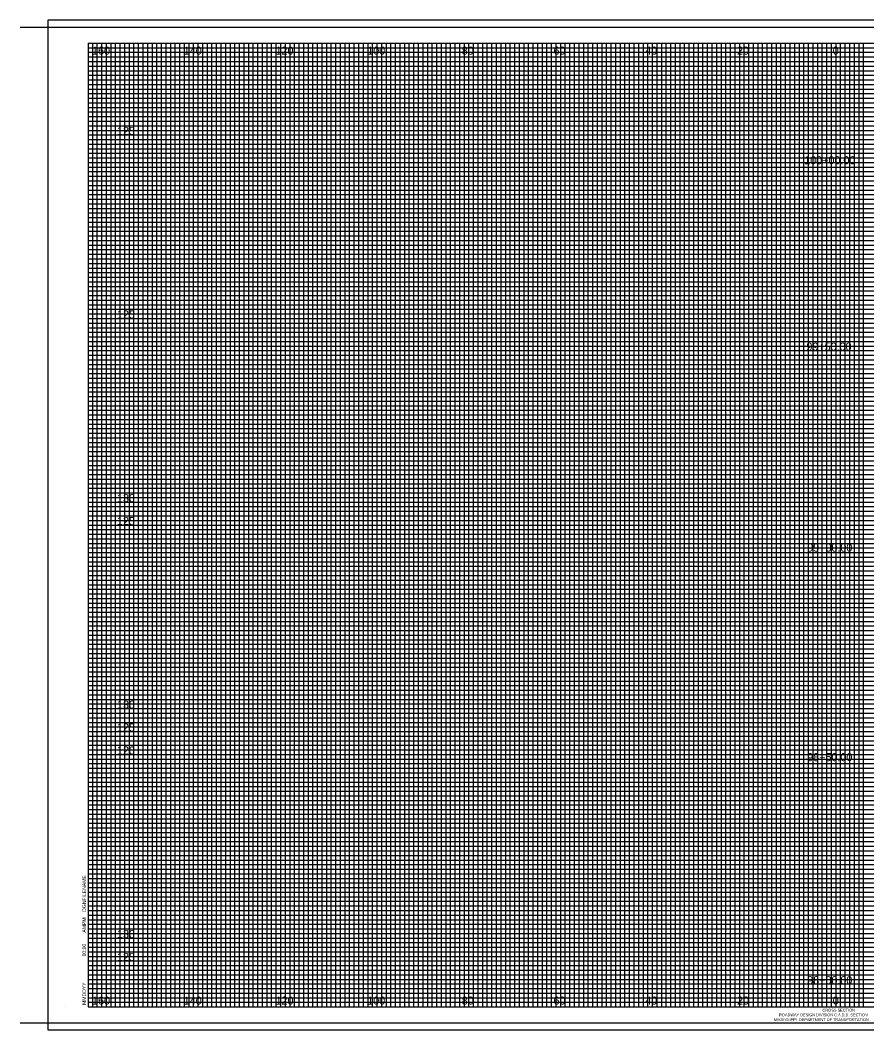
# Model space of a CAD drawing. Extents: x -3604 to 2303, y -13 to 9543.
# Drawn here: x -3604.5 to -3420, y 6454.1 to 6674.1 of the extents above; entities that cross this region are included whole.
import ezdxf

# ---------------------------------------------------------------- set-up
doc = ezdxf.new("R2010")
doc.units = 0
for name, color, linetype in [('SHEET_BORDER', 7, 'Continuous'), ('SHEET_BORDER_TX', 7, 'Continuous'), ('SHEET_DATE_DGN_TX', 7, 'Continuous'), ('SHEET_PLOTTING_SHAPE', 7, 'Continuous'), ('XS_SHEET_LABELS_ELEVATION', 7, 'Continuous'), ('XS_SHEET_LABELS_OFFSET', 7, 'Continuous'), ('XS_SHEET_LABELS_STATION', 7, 'Continuous'), ('XS_SHEET_MAJOR_GRIDS', 7, 'Continuous'), ('XS_SHEET_MEDIUM_GRIDS', 7, 'Continuous'), ('XS_SHEET_MINOR_GRIDS', 7, 'Continuous')]:
    doc.layers.add(name, color=color, linetype=linetype)

msp = doc.modelspace()

# ---------------------------------------------------------------- linework, layer by layer
at = {"layer": 'SHEET_BORDER'}
for p, q in [((-3604.48, 6672.59), (-3252.48, 6672.59)), ((-3589.68, 6669.09), (-3254.68, 6669.09)), ((-3589.68, 6669.09), (-3589.68, 6459.09)), ((-3445.68, 6459.09), (-3445.68, 6669.09)), ((-3594.68, 6459.09), (-3594.68, 6459.09)), ((-3589.68, 6459.09), (-3254.68, 6459.09)), ((-3604.48, 6455.59), (-3252.48, 6455.59))]:
    msp.add_line(p, q, dxfattribs=at)
at = {"layer": 'SHEET_PLOTTING_SHAPE'}
msp.add_lwpolyline([(-3598.48, 6454.09), (-3252.48, 6454.09), (-3252.48, 6674.09), (-3598.48, 6674.09)], close=True, dxfattribs=at)
at = {"layer": 'XS_SHEET_MAJOR_GRIDS'}
for p, q in [((-3584.68, 6459.09), (-3584.68, 6669.09)), ((-3574.68, 6459.09), (-3574.68, 6669.09)), ((-3564.68, 6459.09), (-3564.68, 6669.09)), ((-3554.68, 6459.09), (-3554.68, 6669.09)), ((-3544.68, 6459.09), (-3544.68, 6669.09)), ((-3534.68, 6459.09), (-3534.68, 6669.09)), ((-3524.68, 6459.09), (-3524.68, 6669.09)), ((-3514.68, 6459.09), (-3514.68, 6669.09)), ((-3504.68, 6459.09), (-3504.68, 6669.09)), ((-3494.68, 6459.09), (-3494.68, 6669.09)), ((-3484.68, 6459.09), (-3484.68, 6669.09)), ((-3474.68, 6459.09), (-3474.68, 6669.09)), ((-3464.68, 6459.09), (-3464.68, 6669.09)), ((-3454.68, 6459.09), (-3454.68, 6669.09)), ((-3444.68, 6459.09), (-3444.68, 6669.09)), ((-3434.68, 6459.09), (-3434.68, 6669.09)), ((-3424.68, 6459.09), (-3424.68, 6669.09)), ((-3589.68, 6659.09), (-3254.68, 6659.09)), ((-3589.68, 6649.09), (-3254.68, 6649.09)), ((-3589.68, 6639.09), (-3254.68, 6639.09)), ((-3589.68, 6629.09), (-3254.68, 6629.09)), ((-3589.68, 6619.09), (-3254.68, 6619.09)), ((-3589.68, 6609.09), (-3254.68, 6609.09)), ((-3589.68, 6599.09), (-3254.68, 6599.09)), ((-3589.68, 6589.09), (-3254.68, 6589.09)), ((-3589.68, 6579.09), (-3254.68, 6579.09)), ((-3589.68, 6569.09), (-3254.68, 6569.09)), ((-3589.68, 6559.09), (-3254.68, 6559.09)), ((-3589.68, 6549.09), (-3254.68, 6549.09)), ((-3589.68, 6539.09), (-3254.68, 6539.09)), ((-3589.68, 6529.09), (-3254.68, 6529.09)), ((-3589.68, 6519.09), (-3254.68, 6519.09)), ((-3589.68, 6509.09), (-3254.68, 6509.09)), ((-3589.68, 6499.09), (-3254.68, 6499.09)), ((-3589.68, 6489.09), (-3254.68, 6489.09)), ((-3589.68, 6479.09), (-3254.68, 6479.09)), ((-3589.68, 6469.09), (-3254.68, 6469.09))]:
    msp.add_line(p, q, dxfattribs=at)
at = {"layer": 'XS_SHEET_MEDIUM_GRIDS'}
for p, q in [((-3579.68, 6459.09), (-3579.68, 6669.09)), ((-3569.68, 6459.09), (-3569.68, 6669.09)), ((-3559.68, 6459.09), (-3559.68, 6669.09)), ((-3549.68, 6459.09), (-3549.68, 6669.09)), ((-3539.68, 6459.09), (-3539.68, 6669.09)), ((-3529.68, 6459.09), (-3529.68, 6669.09)), ((-3519.68, 6459.09), (-3519.68, 6669.09)), ((-3509.68, 6459.09), (-3509.68, 6669.09)), ((-3499.68, 6459.09), (-3499.68, 6669.09)), ((-3489.68, 6459.09), (-3489.68, 6669.09)), ((-3479.68, 6459.09), (-3479.68, 6669.09)), ((-3469.68, 6459.09), (-3469.68, 6669.09)), ((-3459.68, 6459.09), (-3459.68, 6669.09)), ((-3449.68, 6459.09), (-3449.68, 6669.09)), ((-3439.68, 6459.09), (-3439.68, 6669.09)), ((-3429.68, 6459.09), (-3429.68, 6669.09)), ((-3589.68, 6664.09), (-3281.68, 6664.09)), ((-3589.68, 6654.09), (-3254.68, 6654.09)), ((-3589.68, 6644.09), (-3254.68, 6644.09)), ((-3589.68, 6634.09), (-3254.68, 6634.09)), ((-3589.68, 6624.09), (-3254.68, 6624.09)), ((-3589.68, 6614.09), (-3254.68, 6614.09)), ((-3589.68, 6604.09), (-3254.68, 6604.09)), ((-3589.68, 6594.09), (-3254.68, 6594.09)), ((-3589.68, 6584.09), (-3254.68, 6584.09)), ((-3589.68, 6574.09), (-3254.68, 6574.09)), ((-3589.68, 6564.09), (-3254.68, 6564.09)), ((-3589.68, 6554.09), (-3254.68, 6554.09)), ((-3589.68, 6544.09), (-3254.68, 6544.09)), ((-3589.68, 6534.09), (-3254.68, 6534.09)), ((-3589.68, 6524.09), (-3254.68, 6524.09)), ((-3589.68, 6514.09), (-3254.68, 6514.09)), ((-3589.68, 6504.09), (-3254.68, 6504.09)), ((-3589.68, 6494.09), (-3254.68, 6494.09)), ((-3589.68, 6484.09), (-3254.68, 6484.09)), ((-3589.68, 6474.09), (-3254.68, 6474.09)), ((-3589.68, 6464.09), (-3264.68, 6464.09))]:
    msp.add_line(p, q, dxfattribs=at)
at = {"layer": 'XS_SHEET_MINOR_GRIDS'}
for p, q in [((-3588.68, 6459.09), (-3588.68, 6669.09)), ((-3587.68, 6459.09), (-3587.68, 6669.09)), ((-3586.68, 6459.09), (-3586.68, 6669.09)), ((-3585.68, 6459.09), (-3585.68, 6669.09)), ((-3583.68, 6459.09), (-3583.68, 6669.09)), ((-3582.68, 6459.09), (-3582.68, 6669.09)), ((-3581.68, 6459.09), (-3581.68, 6669.09)), ((-3580.68, 6459.09), (-3580.68, 6669.09)), ((-3578.68, 6459.09), (-3578.68, 6669.09)), ((-3577.68, 6459.09), (-3577.68, 6669.09)), ((-3576.68, 6459.09), (-3576.68, 6669.09)), ((-3575.68, 6459.09), (-3575.68, 6669.09)), ((-3573.68, 6459.09), (-3573.68, 6669.09)), ((-3572.68, 6459.09), (-3572.68, 6669.09)), ((-3571.68, 6459.09), (-3571.68, 6669.09)), ((-3570.68, 6459.09), (-3570.68, 6669.09)), ((-3568.68, 6459.09), (-3568.68, 6669.09)), ((-3567.68, 6459.09), (-3567.68, 6669.09)), ((-3566.68, 6459.09), (-3566.68, 6669.09)), ((-3565.68, 6459.09), (-3565.68, 6669.09)), ((-3563.68, 6459.09), (-3563.68, 6669.09)), ((-3562.68, 6459.09), (-3562.68, 6669.09)), ((-3561.68, 6459.09), (-3561.68, 6669.09)), ((-3560.68, 6459.09), (-3560.68, 6669.09)), ((-3558.68, 6459.09), (-3558.68, 6669.09)), ((-3557.68, 6459.09), (-3557.68, 6669.09)), ((-3556.68, 6459.09), (-3556.68, 6669.09)), ((-3555.68, 6459.09), (-3555.68, 6669.09)), ((-3553.68, 6459.09), (-3553.68, 6669.09)), ((-3552.68, 6459.09), (-3552.68, 6669.09)), ((-3551.68, 6459.09), (-3551.68, 6669.09)), ((-3550.68, 6459.09), (-3550.68, 6669.09)), ((-3548.68, 6459.09), (-3548.68, 6669.09)), ((-3547.68, 6459.09), (-3547.68, 6669.09)), ((-3546.68, 6459.09), (-3546.68, 6669.09)), ((-3545.68, 6459.09), (-3545.68, 6669.09)), ((-3543.68, 6459.09), (-3543.68, 6669.09)), ((-3542.68, 6459.09), (-3542.68, 6669.09)), ((-3541.68, 6459.09), (-3541.68, 6669.09)), ((-3540.68, 6459.09), (-3540.68, 6669.09)), ((-3538.68, 6459.09), (-3538.68, 6669.09)), ((-3537.68, 6459.09), (-3537.68, 6669.09)), ((-3536.68, 6459.09), (-3536.68, 6669.09)), ((-3535.68, 6459.09), (-3535.68, 6669.09)), ((-3533.68, 6459.09), (-3533.68, 6669.09)), ((-3532.68, 6459.09), (-3532.68, 6669.09)), ((-3531.68, 6459.09), (-3531.68, 6669.09)), ((-3530.68, 6459.09), (-3530.68, 6669.09)), ((-3528.68, 6459.09), (-3528.68, 6669.09)), ((-3527.68, 6459.09), (-3527.68, 6669.09)), ((-3526.68, 6459.09), (-3526.68, 6669.09)), ((-3525.68, 6459.09), (-3525.68, 6669.09)), ((-3523.68, 6459.09), (-3523.68, 6669.09)), ((-3522.68, 6459.09), (-3522.68, 6669.09)), ((-3521.68, 6459.09), (-3521.68, 6669.09)), ((-3520.68, 6459.09), (-3520.68, 6669.09)), ((-3518.68, 6459.09), (-3518.68, 6669.09)), ((-3517.68, 6459.09), (-3517.68, 6669.09)), ((-3516.68, 6459.09), (-3516.68, 6669.09)), ((-3515.68, 6459.09), (-3515.68, 6669.09)), ((-3513.68, 6459.09), (-3513.68, 6669.09)), ((-3512.68, 6459.09), (-3512.68, 6669.09)), ((-3511.68, 6459.09), (-3511.68, 6669.09)), ((-3510.68, 6459.09), (-3510.68, 6669.09)), ((-3508.68, 6459.09), (-3508.68, 6669.09)), ((-3507.68, 6459.09), (-3507.68, 6669.09)), ((-3506.68, 6459.09), (-3506.68, 6669.09)), ((-3505.68, 6459.09), (-3505.68, 6669.09)), ((-3503.68, 6459.09), (-3503.68, 6669.09)), ((-3502.68, 6459.09), (-3502.68, 6669.09)), ((-3501.68, 6459.09), (-3501.68, 6669.09)), ((-3500.68, 6459.09), (-3500.68, 6669.09)), ((-3498.68, 6459.09), (-3498.68, 6669.09)), ((-3497.68, 6459.09), (-3497.68, 6669.09)), ((-3496.68, 6459.09), (-3496.68, 6669.09)), ((-3495.68, 6459.09), (-3495.68, 6669.09)), ((-3493.68, 6459.09), (-3493.68, 6669.09)), ((-3492.68, 6459.09), (-3492.68, 6669.09)), ((-3491.68, 6459.09), (-3491.68, 6669.09)), ((-3490.68, 6459.09), (-3490.68, 6669.09)), ((-3488.68, 6459.09), (-3488.68, 6669.09)), ((-3487.68, 6459.09), (-3487.68, 6669.09)), ((-3486.68, 6459.09), (-3486.68, 6669.09)), ((-3485.68, 6459.09), (-3485.68, 6669.09)), ((-3483.68, 6459.09), (-3483.68, 6669.09)), ((-3482.68, 6459.09), (-3482.68, 6669.09)), ((-3481.68, 6459.09), (-3481.68, 6669.09)), ((-3480.68, 6459.09), (-3480.68, 6669.09)), ((-3478.68, 6459.09), (-3478.68, 6669.09)), ((-3477.68, 6459.09), (-3477.68, 6669.09)), ((-3476.68, 6459.09), (-3476.68, 6669.09)), ((-3475.68, 6459.09), (-3475.68, 6669.09)), ((-3473.68, 6459.09), (-3473.68, 6669.09)), ((-3472.68, 6459.09), (-3472.68, 6669.09)), ((-3471.68, 6459.09), (-3471.68, 6669.09)), ((-3470.68, 6459.09), (-3470.68, 6669.09)), ((-3468.68, 6459.09), (-3468.68, 6669.09)), ((-3467.68, 6459.09), (-3467.68, 6669.09)), ((-3466.68, 6459.09), (-3466.68, 6669.09)), ((-3465.68, 6459.09), (-3465.68, 6669.09)), ((-3463.68, 6459.09), (-3463.68, 6669.09)), ((-3462.68, 6459.09), (-3462.68, 6669.09)), ((-3461.68, 6459.09), (-3461.68, 6669.09)), ((-3460.68, 6459.09), (-3460.68, 6669.09)), ((-3458.68, 6459.09), (-3458.68, 6669.09)), ((-3457.68, 6459.09), (-3457.68, 6669.09)), ((-3456.68, 6459.09), (-3456.68, 6669.09)), ((-3455.68, 6459.09), (-3455.68, 6669.09)), ((-3453.68, 6459.09), (-3453.68, 6669.09)), ((-3452.68, 6459.09), (-3452.68, 6669.09)), ((-3451.68, 6459.09), (-3451.68, 6669.09)), ((-3450.68, 6459.09), (-3450.68, 6669.09)), ((-3448.68, 6459.09), (-3448.68, 6669.09)), ((-3447.68, 6459.09), (-3447.68, 6669.09)), ((-3446.68, 6459.09), (-3446.68, 6669.09)), ((-3443.68, 6459.09), (-3443.68, 6669.09)), ((-3442.68, 6459.09), (-3442.68, 6669.09)), ((-3441.68, 6459.09), (-3441.68, 6669.09)), ((-3440.68, 6459.09), (-3440.68, 6669.09)), ((-3438.68, 6459.09), (-3438.68, 6669.09)), ((-3437.68, 6459.09), (-3437.68, 6669.09)), ((-3436.68, 6459.09), (-3436.68, 6669.09)), ((-3435.68, 6459.09), (-3435.68, 6669.09)), ((-3433.68, 6459.09), (-3433.68, 6669.09)), ((-3432.68, 6459.09), (-3432.68, 6669.09)), ((-3431.68, 6459.09), (-3431.68, 6669.09)), ((-3430.68, 6459.09), (-3430.68, 6669.09)), ((-3428.68, 6459.09), (-3428.68, 6669.09)), ((-3427.68, 6459.09), (-3427.68, 6669.09)), ((-3426.68, 6459.09), (-3426.68, 6669.09)), ((-3425.68, 6459.09), (-3425.68, 6669.09)), ((-3423.68, 6459.09), (-3423.68, 6669.09)), ((-3422.68, 6459.09), (-3422.68, 6669.09)), ((-3421.68, 6459.09), (-3421.68, 6669.09)), ((-3420.68, 6459.09), (-3420.68, 6669.09)), ((-3589.68, 6668.09), (-3281.68, 6668.09)), ((-3589.68, 6667.09), (-3281.68, 6667.09)), ((-3589.68, 6666.09), (-3281.68, 6666.09)), ((-3589.68, 6665.09), (-3281.68, 6665.09)), ((-3589.68, 6663.09), (-3281.68, 6663.09)), ((-3589.68, 6662.09), (-3281.68, 6662.09)), ((-3589.68, 6661.09), (-3281.68, 6661.09)), ((-3589.68, 6660.09), (-3254.68, 6660.09)), ((-3589.68, 6658.09), (-3254.68, 6658.09)), ((-3589.68, 6657.09), (-3254.68, 6657.09)), ((-3589.68, 6656.09), (-3254.68, 6656.09)), ((-3589.68, 6655.09), (-3254.68, 6655.09)), ((-3589.68, 6653.09), (-3254.68, 6653.09)), ((-3589.68, 6652.09), (-3254.68, 6652.09)), ((-3589.68, 6651.09), (-3254.68, 6651.09)), ((-3589.68, 6650.09), (-3254.68, 6650.09)), ((-3589.68, 6648.09), (-3254.68, 6648.09)), ((-3589.68, 6647.09), (-3254.68, 6647.09)), ((-3589.68, 6646.09), (-3254.68, 6646.09)), ((-3589.68, 6645.09), (-3254.68, 6645.09)), ((-3589.68, 6643.09), (-3254.68, 6643.09)), ((-3589.68, 6642.09), (-3254.68, 6642.09)), ((-3589.68, 6641.09), (-3254.68, 6641.09)), ((-3589.68, 6640.09), (-3254.68, 6640.09)), ((-3589.68, 6638.09), (-3254.68, 6638.09)), ((-3589.68, 6637.09), (-3254.68, 6637.09)), ((-3589.68, 6636.09), (-3254.68, 6636.09)), ((-3589.68, 6635.09), (-3254.68, 6635.09)), ((-3589.68, 6633.09), (-3254.68, 6633.09)), ((-3589.68, 6632.09), (-3254.68, 6632.09)), ((-3589.68, 6631.09), (-3254.68, 6631.09)), ((-3589.68, 6630.09), (-3254.68, 6630.09)), ((-3589.68, 6628.09), (-3254.68, 6628.09)), ((-3589.68, 6627.09), (-3254.68, 6627.09)), ((-3589.68, 6626.09), (-3254.68, 6626.09)), ((-3589.68, 6625.09), (-3254.68, 6625.09)), ((-3589.68, 6623.09), (-3254.68, 6623.09)), ((-3589.68, 6622.09), (-3254.68, 6622.09)), ((-3589.68, 6621.09), (-3254.68, 6621.09)), ((-3589.68, 6620.09), (-3254.68, 6620.09)), ((-3589.68, 6618.09), (-3254.68, 6618.09)), ((-3589.68, 6617.09), (-3254.68, 6617.09)), ((-3589.68, 6616.09), (-3254.68, 6616.09)), ((-3589.68, 6615.09), (-3254.68, 6615.09)), ((-3589.68, 6613.09), (-3254.68, 6613.09)), ((-3589.68, 6612.09), (-3254.68, 6612.09)), ((-3589.68, 6611.09), (-3254.68, 6611.09)), ((-3589.68, 6610.09), (-3254.68, 6610.09)), ((-3589.68, 6608.09), (-3254.68, 6608.09)), ((-3589.68, 6607.09), (-3254.68, 6607.09)), ((-3589.68, 6606.09), (-3254.68, 6606.09)), ((-3589.68, 6605.09), (-3254.68, 6605.09)), ((-3589.68, 6603.09), (-3254.68, 6603.09)), ((-3589.68, 6602.09), (-3254.68, 6602.09)), ((-3589.68, 6601.09), (-3254.68, 6601.09)), ((-3589.68, 6600.09), (-3254.68, 6600.09)), ((-3589.68, 6598.09), (-3254.68, 6598.09)), ((-3589.68, 6597.09), (-3254.68, 6597.09)), ((-3589.68, 6596.09), (-3254.68, 6596.09)), ((-3589.68, 6595.09), (-3254.68, 6595.09)), ((-3589.68, 6593.09), (-3254.68, 6593.09)), ((-3589.68, 6592.09), (-3254.68, 6592.09)), ((-3589.68, 6591.09), (-3254.68, 6591.09)), ((-3589.68, 6590.09), (-3254.68, 6590.09)), ((-3589.68, 6588.09), (-3254.68, 6588.09)), ((-3589.68, 6587.09), (-3254.68, 6587.09)), ((-3589.68, 6586.09), (-3254.68, 6586.09)), ((-3589.68, 6585.09), (-3254.68, 6585.09)), ((-3589.68, 6583.09), (-3254.68, 6583.09)), ((-3589.68, 6582.09), (-3254.68, 6582.09)), ((-3589.68, 6581.09), (-3254.68, 6581.09)), ((-3589.68, 6580.09), (-3254.68, 6580.09)), ((-3589.68, 6578.09), (-3254.68, 6578.09)), ((-3589.68, 6577.09), (-3254.68, 6577.09)), ((-3589.68, 6576.09), (-3254.68, 6576.09)), ((-3589.68, 6575.09), (-3254.68, 6575.09)), ((-3589.68, 6573.09), (-3254.68, 6573.09)), ((-3589.68, 6572.09), (-3254.68, 6572.09)), ((-3589.68, 6571.09), (-3254.68, 6571.09)), ((-3589.68, 6570.09), (-3254.68, 6570.09)), ((-3589.68, 6568.09), (-3254.68, 6568.09)), ((-3589.68, 6567.09), (-3254.68, 6567.09)), ((-3589.68, 6566.09), (-3254.68, 6566.09)), ((-3589.68, 6565.09), (-3254.68, 6565.09)), ((-3589.68, 6563.09), (-3254.68, 6563.09)), ((-3589.68, 6562.09), (-3254.68, 6562.09)), ((-3589.68, 6561.09), (-3254.68, 6561.09)), ((-3589.68, 6560.09), (-3254.68, 6560.09)), ((-3589.68, 6558.09), (-3254.68, 6558.09)), ((-3589.68, 6557.09), (-3254.68, 6557.09)), ((-3589.68, 6556.09), (-3254.68, 6556.09)), ((-3589.68, 6555.09), (-3254.68, 6555.09)), ((-3589.68, 6553.09), (-3254.68, 6553.09)), ((-3589.68, 6552.09), (-3254.68, 6552.09)), ((-3589.68, 6551.09), (-3254.68, 6551.09)), ((-3589.68, 6550.09), (-3254.68, 6550.09)), ((-3589.68, 6548.09), (-3254.68, 6548.09)), ((-3589.68, 6547.09), (-3254.68, 6547.09)), ((-3589.68, 6546.09), (-3254.68, 6546.09)), ((-3589.68, 6545.09), (-3254.68, 6545.09)), ((-3589.68, 6543.09), (-3254.68, 6543.09)), ((-3589.68, 6542.09), (-3254.68, 6542.09)), ((-3589.68, 6541.09), (-3254.68, 6541.09)), ((-3589.68, 6540.09), (-3254.68, 6540.09)), ((-3589.68, 6538.09), (-3254.68, 6538.09)), ((-3589.68, 6537.09), (-3254.68, 6537.09)), ((-3589.68, 6536.09), (-3254.68, 6536.09)), ((-3589.68, 6535.09), (-3254.68, 6535.09)), ((-3589.68, 6533.09), (-3254.68, 6533.09)), ((-3589.68, 6532.09), (-3254.68, 6532.09)), ((-3589.68, 6531.09), (-3254.68, 6531.09)), ((-3589.68, 6530.09), (-3254.68, 6530.09)), ((-3589.68, 6528.09), (-3254.68, 6528.09)), ((-3589.68, 6527.09), (-3254.68, 6527.09)), ((-3589.68, 6526.09), (-3254.68, 6526.09)), ((-3589.68, 6525.09), (-3254.68, 6525.09)), ((-3589.68, 6523.09), (-3254.68, 6523.09)), ((-3589.68, 6522.09), (-3254.68, 6522.09)), ((-3589.68, 6521.09), (-3254.68, 6521.09)), ((-3589.68, 6520.09), (-3254.68, 6520.09)), ((-3589.68, 6518.09), (-3254.68, 6518.09)), ((-3589.68, 6517.09), (-3254.68, 6517.09)), ((-3589.68, 6516.09), (-3254.68, 6516.09)), ((-3589.68, 6515.09), (-3254.68, 6515.09)), ((-3589.68, 6513.09), (-3254.68, 6513.09)), ((-3589.68, 6512.09), (-3254.68, 6512.09)), ((-3589.68, 6511.09), (-3254.68, 6511.09)), ((-3589.68, 6510.09), (-3254.68, 6510.09)), ((-3589.68, 6508.09), (-3254.68, 6508.09)), ((-3589.68, 6507.09), (-3254.68, 6507.09)), ((-3589.68, 6506.09), (-3254.68, 6506.09)), ((-3589.68, 6505.09), (-3254.68, 6505.09)), ((-3589.68, 6503.09), (-3254.68, 6503.09)), ((-3589.68, 6502.09), (-3254.68, 6502.09)), ((-3589.68, 6501.09), (-3254.68, 6501.09)), ((-3589.68, 6500.09), (-3254.68, 6500.09)), ((-3589.68, 6498.09), (-3254.68, 6498.09)), ((-3589.68, 6497.09), (-3254.68, 6497.09)), ((-3589.68, 6496.09), (-3254.68, 6496.09)), ((-3589.68, 6495.09), (-3254.68, 6495.09)), ((-3589.68, 6493.09), (-3254.68, 6493.09)), ((-3589.68, 6492.09), (-3254.68, 6492.09)), ((-3589.68, 6491.09), (-3254.68, 6491.09)), ((-3589.68, 6490.09), (-3254.68, 6490.09)), ((-3589.68, 6488.09), (-3254.68, 6488.09)), ((-3589.68, 6487.09), (-3254.68, 6487.09)), ((-3589.68, 6486.09), (-3254.68, 6486.09)), ((-3589.68, 6485.09), (-3254.68, 6485.09)), ((-3589.68, 6483.09), (-3254.68, 6483.09)), ((-3589.68, 6482.09), (-3254.68, 6482.09)), ((-3589.68, 6481.09), (-3254.68, 6481.09)), ((-3589.68, 6480.09), (-3254.68, 6480.09)), ((-3589.68, 6480.09), (-3254.68, 6480.09)), ((-3589.68, 6480.09), (-3254.68, 6480.09)), ((-3589.68, 6478.09), (-3254.68, 6478.09)), ((-3589.68, 6477.09), (-3254.68, 6477.09)), ((-3589.68, 6476.09), (-3254.68, 6476.09)), ((-3589.68, 6475.09), (-3254.68, 6475.09)), ((-3589.68, 6473.09), (-3254.68, 6473.09)), ((-3589.68, 6472.09), (-3254.68, 6472.09)), ((-3589.68, 6471.09), (-3254.68, 6471.09)), ((-3589.68, 6470.09), (-3254.68, 6470.09)), ((-3589.68, 6468.09), (-3264.68, 6468.09)), ((-3589.68, 6467.09), (-3264.68, 6467.09)), ((-3589.68, 6466.09), (-3264.68, 6466.09)), ((-3589.68, 6465.09), (-3264.68, 6465.09)), ((-3589.68, 6465.09), (-3264.68, 6465.09)), ((-3589.68, 6465.09), (-3264.68, 6465.09)), ((-3589.68, 6463.09), (-3264.68, 6463.09)), ((-3589.68, 6462.09), (-3264.68, 6462.09)), ((-3589.68, 6461.09), (-3264.68, 6461.09)), ((-3589.68, 6460.09), (-3264.68, 6460.09))]:
    msp.add_line(p, q, dxfattribs=at)

# ---------------------------------------------------------------- texts
at = {"layer": 'SHEET_BORDER_TX'}
for s, height, p in [('ROADWAY DESIGN DIVISION C.A.D.D. SECTION', 0.61, (-3439.08, 6457.04)), ('CROSS SECTION', 0.62, (-3429.64, 6458.06)), ('MISSISSIPPI  DEPARTMENT OF TRANSPORTATION', 0.61, (-3440.24, 6456.01))]:
    msp.add_text(s, height=height, dxfattribs=at).set_placement(p)
at = {"layer": 'SHEET_DATE_DGN_TX'}
for s, p in [('DGNFILENAME', (-3590.15, 6479.79)), ('AMPM', (-3590.15, 6475.27)), ('00:00', (-3590.15, 6470.09)), ('MMDDYY', (-3590.15, 6459.51))]:
    msp.add_text(s, height=0.8, rotation=90, dxfattribs=at).set_placement(p)
at = {"layer": 'XS_SHEET_LABELS_ELEVATION'}
for s, p in [('  125  ', (-3584.68, 6649.09)), ('  125  ', (-3584.68, 6609.09)), ('  130  ', (-3584.68, 6569.09)), ('  125  ', (-3584.68, 6564.09)), ('  130  ', (-3584.68, 6524.09)), ('  125  ', (-3584.68, 6519.09)), ('  120  ', (-3584.68, 6514.09)), ('  130  ', (-3584.68, 6474.09)), ('  125  ', (-3584.68, 6469.09))]:
    msp.add_text(s, height=1.75, dxfattribs=at).set_placement(p)
at = {"layer": 'XS_SHEET_LABELS_OFFSET'}
for s, p in [('  160  ', (-3590.11, 6666.59)), ('  140  ', (-3570.13, 6666.59)), ('  120  ', (-3550.13, 6666.59)), ('  100  ', (-3530.13, 6666.59)), ('  80  ', (-3509.56, 6666.59)), ('  60  ', (-3489.55, 6666.59)), ('  40  ', (-3469.56, 6666.59)), ('  20  ', (-3449.56, 6666.59)), ('  0  ', (-3428.71, 6666.59)), ('  0  ', (-3428.71, 6666.59)), ('  160  ', (-3590.11, 6459.59)), ('  140  ', (-3570.13, 6459.59)), ('  120  ', (-3550.13, 6459.59)), ('  100  ', (-3530.13, 6459.59)), ('  80  ', (-3509.56, 6459.59)), ('  60  ', (-3489.55, 6459.59)), ('  40  ', (-3469.56, 6459.59)), ('  20  ', (-3449.56, 6459.59)), ('  0  ', (-3428.71, 6459.59)), ('  0  ', (-3428.71, 6459.59))]:
    msp.add_text(s, height=1.75, dxfattribs=at).set_placement(p)
at = {"layer": 'XS_SHEET_LABELS_STATION'}
for s, p in [('  100+00.00  ', (-3434.91, 6642.7)), ('  99+50.00  ', (-3434.43, 6602.09)), ('  99+00.00  ', (-3434.26, 6558.29)), ('  98+50.00  ', (-3434.26, 6512.63)), ('  98+00.00  ', (-3434.26, 6464.02))]:
    msp.add_text(s, height=1.75, dxfattribs=at).set_placement(p)

doc.saveas('drawing.dxf')
